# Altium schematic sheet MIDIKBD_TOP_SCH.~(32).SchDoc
size A4
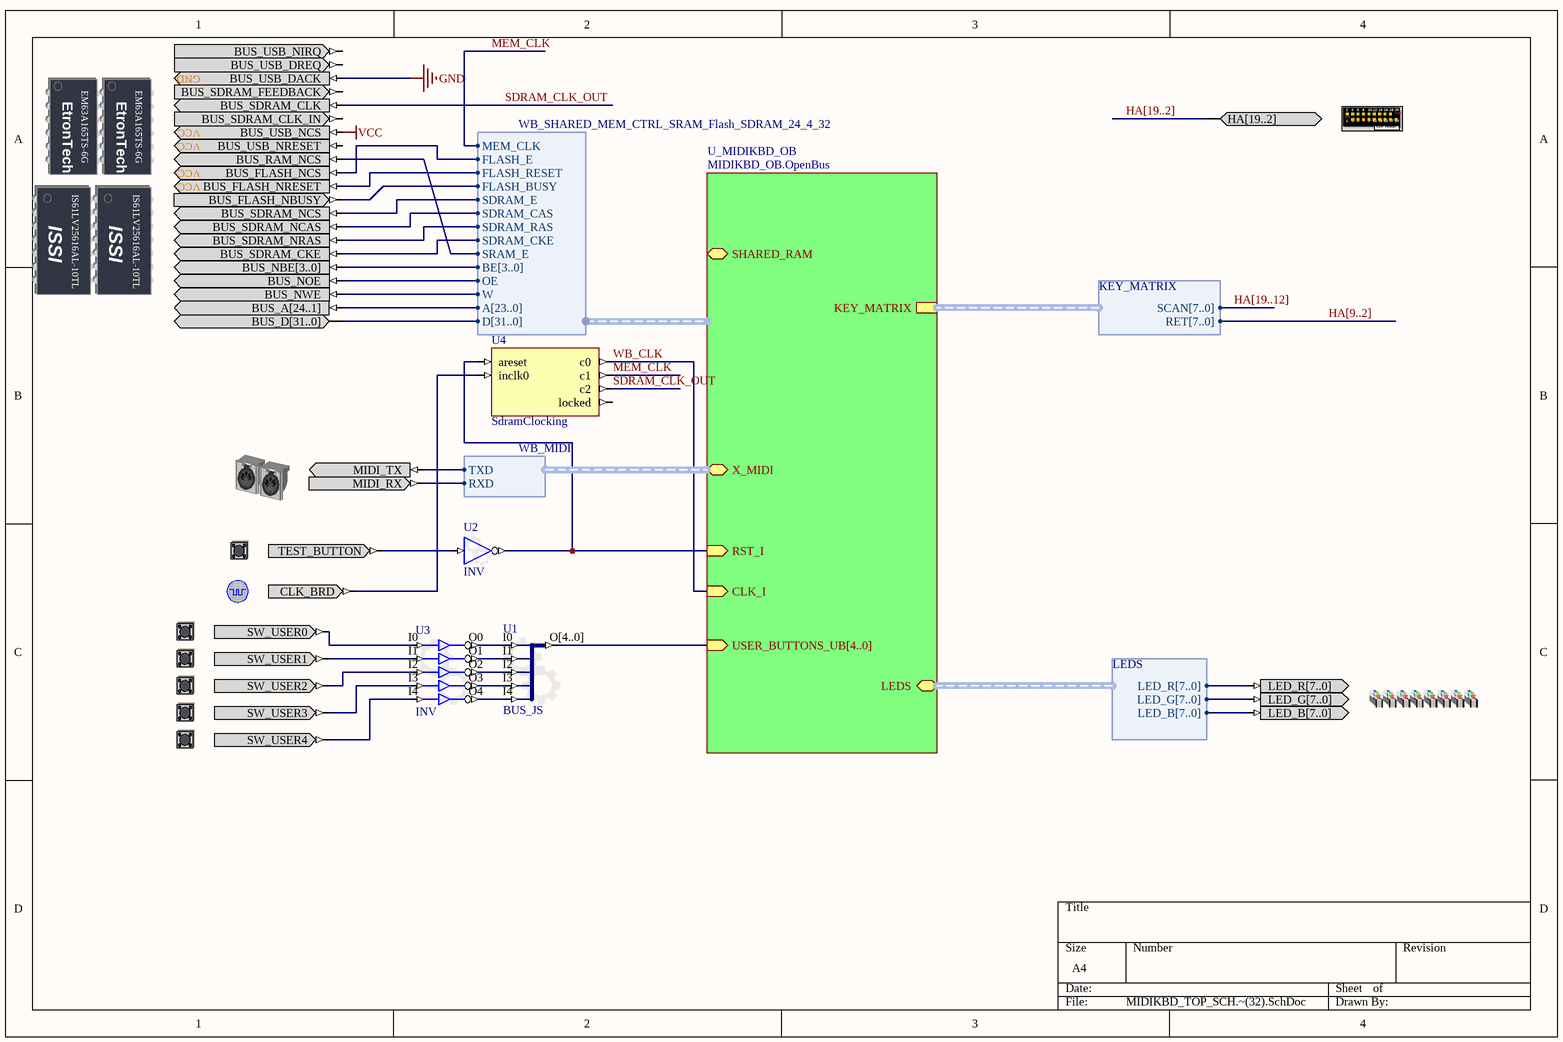
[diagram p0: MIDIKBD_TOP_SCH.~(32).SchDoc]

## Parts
(Parts that share a designator on the sheet are numbered #1, #2 ... from top to bottom, then left to right.)
?#1  USER_HEADER_A  (value not drawn)
?#2  SHARED_SRAM_SDRAM  (value not drawn)
?#3  MIDI  (value not drawn)
?#4  TEST_BUTTON  (value not drawn)
?#5  CLOCK_BOARD  (value not drawn)
?#6  USER_BUTTON0  (value not drawn)
?#7  USER_BUTTON1  (value not drawn)
?#8  USER_BUTTON2  (value not drawn)
?#9  LEDS_RGB  (value not drawn)
?#10  USER_BUTTON3  (value not drawn)
?#11  USER_BUTTON4  (value not drawn)
U1  BUS_JS
U2  INV
U3  INV
U4  SdramClocking

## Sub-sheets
U_MIDIKBD_OB = MIDIKBD_OB.OpenBus: KEY_MATRIX (harness KEY_MATRIX), RST_I (in), CLK_I (in), LEDS (harness LEDS), X_MIDI (harness WB_MIDI), USER_BUTTONS_UB[4..0] (in), SHARED_RAM (harness WB_SHARED_MEM_CTRL_SRAM_Flash_SDRAM_24_4_32)

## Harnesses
KEY_MATRIX: SCAN[7..0], RET[7..0]
LEDS: LED_R[7..0], LED_G[7..0], LED_B[7..0]
WB_MIDI: RXD, TXD
WB_SHARED_MEM_CTRL_SRAM_Flash_SDRAM_24_4_32: D[31..0], A[23..0], W, OE, BE[3..0], SRAM_E, SDRAM_CKE, SDRAM_RAS, SDRAM_CAS, SDRAM_E, FLASH_BUSY, FLASH_RESET, FLASH_E, MEM_CLK

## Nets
GND: ?#2.BUS_USB_DACK
VCC: ?#2.BUS_USB_NCS
MEM_CLK: U4.c1 ; harness WB_SHARED_MEM_CTRL_SRAM_Flash_SDRAM_24_4_32.MEM_CLK
SDRAM_CLK_OUT: ?#2.BUS_SDRAM_CLK U4.c2
WB_CLK: U4.c0 ; sheet U_MIDIKBD_OB/CLK_I
Net?#2_BUS_FLASH_NBUSY: ?#2.BUS_FLASH_NBUSY ; harness WB_SHARED_MEM_CTRL_SRAM_Flash_SDRAM_24_4_32.FLASH_BUSY
Net?#2_BUS_FLASH_NCS: ?#2.BUS_FLASH_NCS ; harness WB_SHARED_MEM_CTRL_SRAM_Flash_SDRAM_24_4_32.FLASH_E
Net?#2_BUS_FLASH_NRESET: ?#2.BUS_FLASH_NRESET ; harness WB_SHARED_MEM_CTRL_SRAM_Flash_SDRAM_24_4_32.FLASH_RESET
Net?#2_BUS_NOE: ?#2.BUS_NOE ; harness WB_SHARED_MEM_CTRL_SRAM_Flash_SDRAM_24_4_32.OE
Net?#2_BUS_NWE: ?#2.BUS_NWE ; harness WB_SHARED_MEM_CTRL_SRAM_Flash_SDRAM_24_4_32.W
Net?#2_BUS_RAM_NCS: ?#2.BUS_RAM_NCS ; harness WB_SHARED_MEM_CTRL_SRAM_Flash_SDRAM_24_4_32.SRAM_E
Net?#2_BUS_SDRAM_CKE: ?#2.BUS_SDRAM_CKE ; harness WB_SHARED_MEM_CTRL_SRAM_Flash_SDRAM_24_4_32.SDRAM_CKE
Net?#2_BUS_SDRAM_NCAS: ?#2.BUS_SDRAM_NCAS ; harness WB_SHARED_MEM_CTRL_SRAM_Flash_SDRAM_24_4_32.SDRAM_CAS
Net?#2_BUS_SDRAM_NCS: ?#2.BUS_SDRAM_NCS ; harness WB_SHARED_MEM_CTRL_SRAM_Flash_SDRAM_24_4_32.SDRAM_E
Net?#2_BUS_SDRAM_NRAS: ?#2.BUS_SDRAM_NRAS ; harness WB_SHARED_MEM_CTRL_SRAM_Flash_SDRAM_24_4_32.SDRAM_RAS
Net?#3_MIDI_RX: ?#3.MIDI_RX ; sheet U_MIDIKBD_OB/X_MIDI.RXD
Net?#3_MIDI_TX: ?#3.MIDI_TX ; sheet U_MIDIKBD_OB/X_MIDI.TXD
Net?#4_TEST_BUTTON: ?#4.TEST_BUTTON U2.I
Net?#5_CLK_BRD: ?#5.CLK_BRD U4.inclk0
Net?#6_SW_USER0: ?#6.SW_USER0 U3.I0
Net?#7_SW_USER1: ?#7.SW_USER1 U3.I1
Net?#8_SW_USER2: ?#8.SW_USER2 U3.I2
Net?#10_SW_USER3: ?#10.SW_USER3 U3.I3
Net?#11_SW_USER4: ?#11.SW_USER4 U3.I4
NetU1_I0: U1.I0 U3.O0
NetU1_I1: U1.I1 U3.O1
NetU1_I2: U1.I2 U3.O2
NetU1_I3: U1.I3 U3.O3
NetU1_I4: U1.I4 U3.O4
NetU2_O: U2.O U4.areset ; sheet U_MIDIKBD_OB/RST_I

Not connected (* = marked no-connect by the designer): ?#1 HA[19..2]; ?#2 BUS_A[24..1] BUS_D[31..0] BUS_NBE[3..0] BUS_SDRAM_CLK_IN BUS_SDRAM_FEEDBACK BUS_USB_DREQ BUS_USB_NIRQ BUS_USB_NRESET; ?#9 LED_B[7..0] LED_G[7..0] LED_R[7..0]; U1 O[4..0]; U4 locked

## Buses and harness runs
bus HA[9..2]
bus HA[19..2]
bus HA[19..12]

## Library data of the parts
?#1 = USER_HEADER_A: User Header A; PortComponent: True
?#2 = SHARED_SRAM_SDRAM: Common-Bus SRAM SDRAM; PortComponent: True
?#3 = MIDI: MIDI Connector; PortComponent: True
?#4 = TEST_BUTTON: Test / Reset Button; PortComponent: True
?#5 = CLOCK_BOARD: Global System Clock Supply; PortComponent: True
?#6 = USER_BUTTON0: Generic User Button; PortComponent: True
?#7 = USER_BUTTON1: Generic User Button; PortComponent: True
?#8 = USER_BUTTON2: Generic User Button; PortComponent: True
?#9 = LEDS_RGB: LEDS RGB; PortComponent: True
?#10 = USER_BUTTON3: Generic User Button; PortComponent: True
?#11 = USER_BUTTON4: Generic User Button; PortComponent: True
U1 = BUS_JS: Configurable Bus Joiner/Splitter; ConfiguratorName: GENERIC_BUS_JS; ConfigurationParameters: {}Version[1.1]{}SplitterJoinerType[Joiner]{}SignalCount[5]{}SignalWidth0[1]{}GapBelow0[1000000]{}ConnectionType0[Pin]{}SignalWidth1[1]{}GapBelow1[1000000]{}ConnectionType1[Pin]{}SignalWidth2[1]{}GapBelow2[1000000]{}ConnectionType2[Pin]{}SignalWidth3[1]{}GapBelow3[1000000]{}ConnectionType3[Pin]{}SignalWidth4[1]{}GapBelow4[1000000]{}ConnectionType4[Pin]{}ShowPinNames[True]{}
U2 = INV: Configurable Inverter; ConfigurationParameters: {}Version[1.1]{}SignalCount[1]{}SignalWidth0[1]{}OutputOption0[Inverted]{}EnableMode[None]{}ShowPinNames[False]{}; ConfiguratorName: GENERIC_BUFFER
U3 = INV: Configurable Inverter; ConfigurationParameters: {}Version[1.1]{}SignalCount[5]{}SignalWidth0[1]{}OutputOption0[Inverted]{}SignalWidth1[1]{}OutputOption1[Inverted]{}SignalWidth2[1]{}OutputOption2[Inverted]{}SignalWidth3[1]{}OutputOption3[Inverted]{}SignalWidth4[1]{}OutputOption4[Inverted]{}EnableMode[None]{}ShowPinNames[True]{}; ConfiguratorName: GENERIC_BUFFER
U4 = SdramClocking: ChildModel: SdramClocking.QIP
